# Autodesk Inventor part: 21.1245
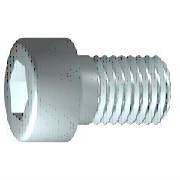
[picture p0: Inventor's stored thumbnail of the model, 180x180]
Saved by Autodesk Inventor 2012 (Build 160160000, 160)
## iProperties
Created: 2006-02
Part Number: 21.1245
Material: Steel, Mild
Description: M6 X 35 SHCS
Document SubType Name: Modeling
Standard: DIN 7984
Designer: Andy Moles
Standards Organization: DIN
Language: en-US
Size Designation: M6 x 35
Categories: <MemberInstance><Categories><Category DisplayName="Fasteners" InternalName="e4da775c-781d-43d5-af7c-5136215cf5a6" Mnemonic="FSTN"><Category DisplayName="Bolts"
Density: 7.86 g/cm^3
Mass: 9.81936 g
Surface Area: 9.72304 cm^2
Volume: 1.24928 cm^3
Author: Andy Moles
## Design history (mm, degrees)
workplane "Work Plane1"
revolve "Body" stored, may be unused: angle "d10" = 90 deg
sketch "Sketch2"
  geometry: L1 (0, -6)-(0, 8) reference; L2 (-6, 0)-(8, 0) reference; L3 (2.309, 0)-(1.155, -2); L4 (1.155, -2)-(-1.155, -2); L5 (-1.155, -2)-(-2.309, 0); L6 (-2.309, 0)-(-1.155, 2); L7 (-1.155, 2)-(1.155, 2); L8 (1.155, 2)-(2.309, 0); 2 further points
  constraints: 12 end point, 1 coincident, 1 horizontal alignment, 1 point on line, 12 other
extrude "Slot" join sketch "Sketch2" stored distance "d11" = 10; taper "d12" = 0 deg
body "Solid1"
fillet "Fillet1" dims "d17" = 0.6 (= RR)
feature "Thread" dims "d13" = 18 (= GEL), "d14" = 0
chamfer "Chamfer1" distance "d15" = 0.61345 (= -0.5 x SPD + 0.5 x GD); stored, may be unused: second distance "d16" = 0.61345 (= GUL), angle "d27" = 45 deg
sketch "Sketch1"
  geometry: L1 (0.333, 0)-(35, 0); L2 (35, 0)-(35, 3); L3 (35, 3)-(17, 3); L4 (17, 3)-(16.386, 3); L5 (16.386, 3)-(0, 3); L6 (0, 3)-(0, 5); L7 (0, 5)-(-4, 5); L8 (-4, 5)-(-4, 2.309); L9 (-4, 2.309)-(-1, 2.309); L10 (-1, 2.309)-(0.333, 0); L11 (-7.9, 0)-(46.7, 0) reference; L12 (0, -0.5)-(0, 6.5) reference; L13 (17, 3)-(0, 3)
  constraints: 22 end point, 6 parallel, 2 collinear, 2 perpendicular, 1 horizontal, 1 midpoint
  dimensions: "d1" = 18 distance from line of L3.end L2 (= GEL); "d2" = 0.61355 distance of L4.end L3.end (computed from GAL); "d3" = 4 distance between parallel lines of L8 L6 (= KOH); "d4" = 3 distance of L8.end L9.end (= INTI); "d5" = 60 deg angle of L10 L1; "d6" = 6 diameter of L3 L1 (= GD); "d7" = 6 diameter of L5 L1 (= BDM); "d8" = 4.6188 diameter of L9 L1 (= 1.1547 x SW); "d9" = 10 diameter of L7 L1 (= KOD); "d26" = 35 distance between parallel lines of L12 L2 (= NLG)
other parameters: "GD" = 6 (= NND) [user parameter; used in 2 equation terms], "NLG" = 35 [user parameter; used in 1 equation term], "GEL" = 18 [user parameter; used in 2 equation terms], "KOD" = 10 [user parameter; used in 1 equation term], "KOH" = 4 [user parameter; used in 1 equation term], "INTI" = 3 [user parameter; used in 1 equation term], "GAL" = 0.61345 (= 0.61345 x PTC) [user parameter; used in 1 equation term], "GUL" = 0.61345 (= 0.61345 x PTC) [user parameter; used in 1 equation term], "BDM" = 6 (= NND) [user parameter; used in 1 equation term], "SW" = 4 [user parameter; used in 2 equation terms], "RR" = 0.6 [user parameter; used in 1 equation term], "SPD" = 4.7731 (= NND - 1.2269 x PTC) [user parameter; used in 1 equation term], "d19" = 0, "d28" = 0, "d29" = 0, "TOA" = 30 deg [user parameter], "GD1" = 4.7731 (= THREADDIA - 1.2269 x PTC) [user parameter], "THREADDIA" = 6 [user parameter; used in 1 equation term], "FAWI" = 45 deg [user parameter], "ANG" = 120 deg [user parameter], "PTC" = 1 [user parameter; used in 5 equation terms], "NND" = 6 [user parameter; used in 3 equation terms], "E0" = 4.62 (= 1.155 x SW) [user parameter]
